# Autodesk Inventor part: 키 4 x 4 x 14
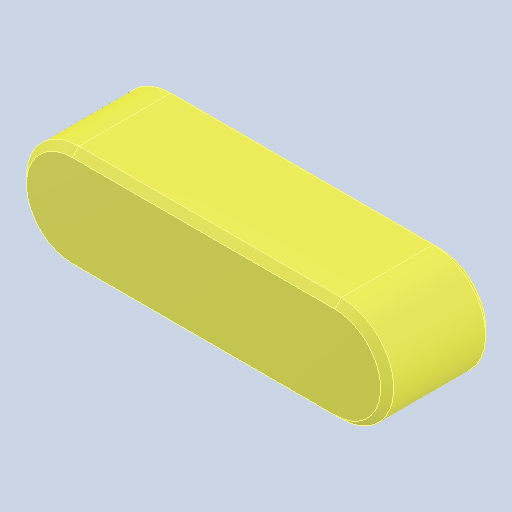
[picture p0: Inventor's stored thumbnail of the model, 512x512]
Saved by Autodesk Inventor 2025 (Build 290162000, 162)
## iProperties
Created: 2024-07
Part Number: 키 4 x 4 x 14
Material: 강철, 연강
Description: 키 및 해당 키홈
Document SubType Name: Modeling
Designer: hsj03
Density: 7.85 g/cm^3
Appearance: 기본값
Author: jhkim
Sending System: Autodesk Inventor 2025
Preprocessor: ST-DEVELOPER v20
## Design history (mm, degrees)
feature "Solid1"
node "솔리드1"
